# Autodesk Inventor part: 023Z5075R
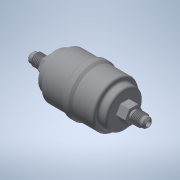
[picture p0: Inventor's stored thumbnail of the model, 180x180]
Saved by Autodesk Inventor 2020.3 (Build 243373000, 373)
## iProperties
Created: 2022-08
Part Number: 023Z5075R
Material: Generic
Document SubType Name: Modeling
Designer: U403152
Density: 1 g/cm^3
Appearance: Default
Author: U403152
SAPCGUIDELINE1: 500B0598
REGION: EU
DESCRIPTION1: =<Description>
ATEX_APPROVAL: No
FM_APPROVAL: No
PED_APPROVAL: No
Title: C:\Users\U403152\OneDrive - Danfoss\Desktop\DCL 3D\023Z5075R.stp
Sending System: Autodesk Inventor 2020
Preprocessor: ST-DEVELOPER v18.1
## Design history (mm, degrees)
sketch "Sketch1"
  geometry: 1 further point
  constraints: 1 other
feature "Solid1"
node "DCL 32"
